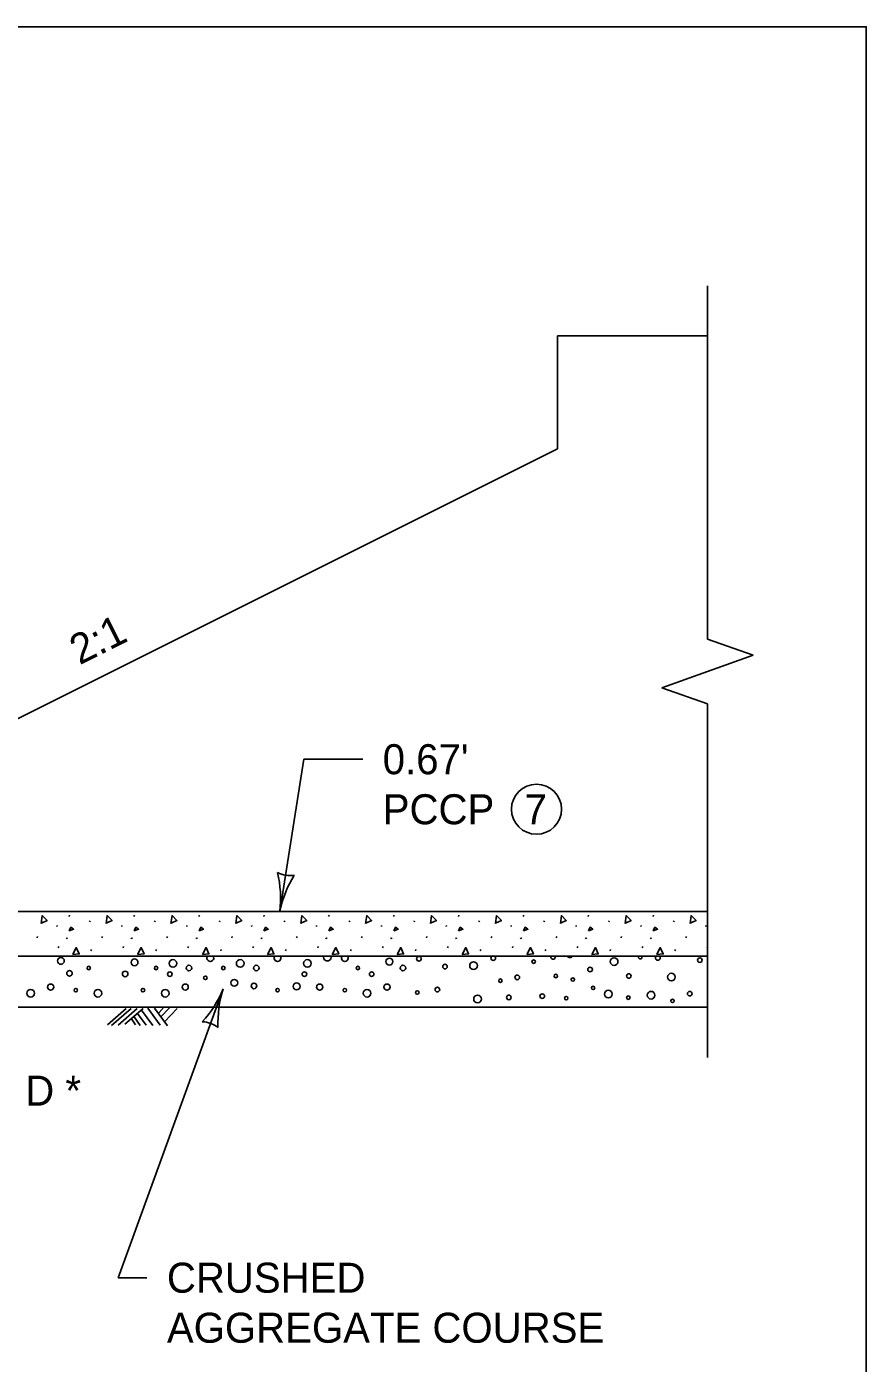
# Model space of a CAD drawing. Extents: x 49991.4 to 50021, y 49987.6 to 50011.4.
# Drawn here: x 50012.898 to 50014.575, y 49989.416 to 49992.087 of the extents above; entities that cross this region are included whole.
import ezdxf

# ---------------------------------------------------------------- set-up
doc = ezdxf.new("R2010")
doc.units = 0
for name, color, linetype in [('Level 1', 7, 'Continuous'), ('Level 2', 7, 'Continuous'), ('Level 3', 7, 'Continuous'), ('Level 6', 7, 'Continuous')]:
    doc.layers.add(name, color=color, linetype=linetype)

msp = doc.modelspace()

# ---------------------------------------------------------------- linework, layer by layer
at = {"layer": 'Level 1'}
for p, q in [((50013.9584, 49991.4692), (50013.9584, 49991.2434)), ((50013.9584, 49991.4692), (50014.2581, 49991.4692)), ((50013.9584, 49991.2434), (50012.1786, 49990.3535)), ((50012.2956, 49990.3188), (50014.2581, 49990.3188)), ((50012.2956, 49990.2297), (50014.2581, 49990.2297)), ((50012.1786, 49990.1273), (50014.2581, 49990.1273)), ((50013.0965, 49990.1248), (50013.0595, 49990.0925)), ((50013.1063, 49990.1248), (50013.0674, 49990.0908)), ((50013.1186, 49990.1249), (50013.0805, 49990.0918)), ((50013.1302, 49990.1252), (50013.0938, 49990.0934)), ((50013.1188, 49990.1152), (50013.1362, 49990.0914)), ((50013.1271, 49990.1218), (50013.1496, 49990.0909)), ((50013.14, 49990.1255), (50013.1646, 49990.0919)), ((50013.1528, 49990.1257), (50013.1788, 49990.0901)), ((50013.1598, 49990.1143), (50013.1706, 49990.1257)), ((50013.1651, 49990.1074), (50013.1835, 49990.1268)), ((50013.1733, 49990.0982), (50013.1987, 49990.1252)), ((50013.1069, 49990.1041), (50013.1153, 49990.0925)), ((50013.1122, 49990.108), (50013.1247, 49990.0908))]:
    msp.add_line(p, q, dxfattribs=at)
msp.add_lwpolyline([(49999.5517, 49992.0867), (50014.5753, 49992.0867), (50014.5753, 49988.387), (49999.5517, 49988.387)], close=True, dxfattribs=at)
for centre, radius in [((50012.966, 49990.22), 0.00684), ((50013.1132, 49990.2171), 0.00684), ((50013.1899, 49990.2149), 0.00766), ((50013.3243, 49990.2149), 0.00766), ((50013.4587, 49990.2149), 0.00766), ((50013.6224, 49990.2185), 0.00684), ((50013.6814, 49990.2243), 0.0046), ((50013.83, 49990.2255), 0.0046), ((50013.9107, 49990.2185), 0.00341), ((50014.0715, 49990.2186), 0.00766), ((50014.2428, 49990.2215), 0.0046), ((50012.9832, 49990.1952), 0.00552), ((50013.0217, 49990.2058), 0.00341), ((50013.0944, 49990.194), 0.00552), ((50013.1562, 49990.2058), 0.00341), ((50013.1837, 49990.1935), 0.0046), ((50013.222, 49990.2058), 0.00552), ((50013.2906, 49990.2058), 0.00341), ((50013.3565, 49990.2058), 0.00552), ((50013.4526, 49990.1935), 0.0046), ((50013.5595, 49990.2058), 0.00341), ((50013.587, 49990.1935), 0.0046), ((50013.6496, 49990.2058), 0.00552), ((50013.7335, 49990.2087), 0.0046), ((50013.7905, 49990.2105), 0.00766), ((50013.8779, 49990.1871), 0.0046), ((50013.955, 49990.1898), 0.00341), ((50014.0234, 49990.2028), 0.0046), ((50014.1009, 49990.1898), 0.0046), ((50014.186, 49990.1877), 0.00766), ((50012.9455, 49990.1676), 0.00613), ((50012.9957, 49990.1615), 0.00341), ((50013.1301, 49990.1615), 0.00341), ((50013.2144, 49990.1676), 0.00613), ((50013.2547, 49990.1861), 0.00341), ((50013.3126, 49990.1762), 0.00684), ((50013.3519, 49990.17), 0.00552), ((50013.399, 49990.1615), 0.00341), ((50013.4371, 49990.1691), 0.00684), ((50013.4832, 49990.1676), 0.00613), ((50013.5334, 49990.1615), 0.00341), ((50013.6177, 49990.1676), 0.00613), ((50013.7183, 49990.1627), 0.0046), ((50013.8442, 49990.1805), 0.00341), ((50013.989, 49990.1826), 0.00341), ((50014.0295, 49990.166), 0.00341), ((50012.9057, 49990.1554), 0.00766), ((50013.0401, 49990.1554), 0.00766), ((50013.1745, 49990.1554), 0.00766), ((50013.5779, 49990.1554), 0.00766), ((50013.6782, 49990.1569), 0.00341), ((50013.7985, 49990.1439), 0.00766), ((50013.861, 49990.1471), 0.0046), ((50013.9279, 49990.1496), 0.0046), ((50013.9759, 49990.1455), 0.00341), ((50014.0599, 49990.1537), 0.00766), ((50014.0998, 49990.1466), 0.00341), ((50014.1453, 49990.1515), 0.00766), ((50014.1881, 49990.1401), 0.00341), ((50014.2225, 49990.1545), 0.0046)]:
    msp.add_circle(centre, radius, dxfattribs=at)
for centre, radius, start, end in [((50013.2646, 49990.2256), 0.00684, 143.5541, 36.4459), ((50013.399, 49990.2256), 0.00684, 143.5541, 36.4459), ((50013.4984, 49990.2275), 0.00765, 163.8349, 16.1651), ((50013.5334, 49990.2256), 0.00684, 143.5541, 36.4459), ((50013.9495, 49990.228), 0.0046, 159.2385, 20.7615), ((50013.9831, 49990.2345), 0.00766, 219.0724, 320.9276), ((50014.1236, 49990.2273), 0.00341, 135.9278, 44.0722), ((50014.1588, 49990.2259), 0.0046, 125.7802, 54.2198)]:
    msp.add_arc(centre, radius, start, end, dxfattribs=at)
at = {"layer": 'Level 2'}
msp.add_circle((50013.9164, 49990.523), 0.05, dxfattribs=at)
at = {"layer": 'Level 3'}
for p, q in [((50013.4037, 49990.3188), (50013.4515, 49990.623)), ((50013.4515, 49990.623), (50013.5691, 49990.623)), ((50012.9823, 49990.3089), (50012.9834, 49990.3113)), ((50013.0235, 49990.2978), (50013.0245, 49990.3002)), ((50013.112, 49990.3089), (50013.1131, 49990.3113)), ((50013.1531, 49990.2978), (50013.1542, 49990.3002)), ((50013.2416, 49990.3089), (50013.2427, 49990.3113)), ((50013.2828, 49990.2978), (50013.2839, 49990.3002)), ((50013.3713, 49990.3089), (50013.3724, 49990.3113)), ((50013.4124, 49990.2978), (50013.4135, 49990.3002)), ((50013.5009, 49990.3089), (50013.502, 49990.3113)), ((50013.5421, 49990.2978), (50013.5432, 49990.3002)), ((50013.6306, 49990.3089), (50013.6317, 49990.3113)), ((50013.6717, 49990.2978), (50013.6728, 49990.3002)), ((50013.7602, 49990.3089), (50013.7613, 49990.3113)), ((50013.8014, 49990.2978), (50013.8025, 49990.3002)), ((50013.8899, 49990.3089), (50013.891, 49990.3113)), ((50013.931, 49990.2978), (50013.9321, 49990.3002)), ((50014.0196, 49990.3089), (50014.0206, 49990.3113)), ((50014.0607, 49990.2978), (50014.0618, 49990.3002)), ((50014.1492, 49990.3089), (50014.1503, 49990.3113)), ((50014.1904, 49990.2978), (50014.1914, 49990.3002)), ((50012.9582, 49990.291), (50012.9584, 49990.2885)), ((50013.0878, 49990.291), (50013.0881, 49990.2885)), ((50013.2175, 49990.291), (50013.2177, 49990.2885)), ((50013.3471, 49990.291), (50013.3474, 49990.2885)), ((50013.4768, 49990.291), (50013.477, 49990.2885)), ((50013.6064, 49990.291), (50013.6067, 49990.2885)), ((50013.7361, 49990.291), (50013.7364, 49990.2885)), ((50013.8657, 49990.291), (50013.866, 49990.2885)), ((50013.9954, 49990.291), (50013.9957, 49990.2885)), ((50014.1251, 49990.291), (50014.1253, 49990.2885)), ((50014.2547, 49990.291), (50014.255, 49990.2885)), ((50012.9184, 49990.2664), (50012.9195, 49990.2688)), ((50012.9607, 49990.2463), (50012.9617, 49990.2487)), ((50012.9766, 49990.2664), (50012.9777, 49990.2647)), ((50012.9777, 49990.2658), (50012.9788, 49990.2641)), ((50013.0481, 49990.2664), (50013.0492, 49990.2688)), ((50013.0903, 49990.2463), (50013.0914, 49990.2487)), ((50013.1063, 49990.2664), (50013.1074, 49990.2647)), ((50013.1074, 49990.2658), (50013.1085, 49990.2641)), ((50013.1777, 49990.2664), (50013.1788, 49990.2688)), ((50013.22, 49990.2463), (50013.2211, 49990.2487)), ((50013.2359, 49990.2664), (50013.237, 49990.2647)), ((50013.237, 49990.2658), (50013.2381, 49990.2641)), ((50013.3074, 49990.2664), (50013.3085, 49990.2688)), ((50013.3496, 49990.2463), (50013.3507, 49990.2487)), ((50013.3656, 49990.2664), (50013.3667, 49990.2647)), ((50013.3667, 49990.2658), (50013.3678, 49990.2641)), ((50013.4371, 49990.2664), (50013.4381, 49990.2688)), ((50013.4793, 49990.2463), (50013.4804, 49990.2487)), ((50013.4953, 49990.2664), (50013.4963, 49990.2647)), ((50013.4963, 49990.2658), (50013.4974, 49990.2641)), ((50013.5667, 49990.2664), (50013.5678, 49990.2688)), ((50013.6089, 49990.2463), (50013.61, 49990.2487)), ((50013.6249, 49990.2664), (50013.626, 49990.2647)), ((50013.626, 49990.2658), (50013.6271, 49990.2641)), ((50013.6964, 49990.2664), (50013.6974, 49990.2688)), ((50013.7386, 49990.2463), (50013.7397, 49990.2487)), ((50013.7546, 49990.2664), (50013.7556, 49990.2647)), ((50013.7556, 49990.2658), (50013.7567, 49990.2641)), ((50013.826, 49990.2664), (50013.8271, 49990.2688)), ((50013.8682, 49990.2463), (50013.8693, 49990.2487)), ((50013.8842, 49990.2664), (50013.8853, 49990.2647)), ((50013.8853, 49990.2658), (50013.8864, 49990.2641)), ((50013.9557, 49990.2664), (50013.9568, 49990.2688)), ((50013.9979, 49990.2463), (50013.999, 49990.2487)), ((50014.0139, 49990.2664), (50014.015, 49990.2647)), ((50014.015, 49990.2658), (50014.016, 49990.2641)), ((50014.0853, 49990.2664), (50014.0864, 49990.2688)), ((50014.1276, 49990.2463), (50014.1286, 49990.2487)), ((50014.1435, 49990.2664), (50014.1446, 49990.2647)), ((50014.1446, 49990.2658), (50014.1457, 49990.2641)), ((50014.215, 49990.2664), (50014.2161, 49990.2688)), ((50014.2572, 49990.2463), (50014.2581, 49990.2483)), ((50013.0262, 49990.2401), (50013.0273, 49990.2425)), ((50013.1558, 49990.2401), (50013.1569, 49990.2425)), ((50013.2855, 49990.2401), (50013.2866, 49990.2425)), ((50013.4151, 49990.2401), (50013.4162, 49990.2425)), ((50013.5448, 49990.2401), (50013.5459, 49990.2425)), ((50013.6744, 49990.2401), (50013.6755, 49990.2425)), ((50013.8041, 49990.2401), (50013.8052, 49990.2425)), ((50013.9338, 49990.2401), (50013.9348, 49990.2425)), ((50014.0634, 49990.2401), (50014.0645, 49990.2425)), ((50014.1931, 49990.2401), (50014.1941, 49990.2425)), ((50013.2902, 49990.164), (50013.0805, 49989.587)), ((50013.0805, 49989.587), (50013.1379, 49989.587))]:
    msp.add_line(p, q, dxfattribs=at)
for points in [[(50012.9267, 49990.295), (50012.9289, 49990.3104), (50012.9386, 49990.3004), (50012.927, 49990.2951)], [(50013.0564, 49990.295), (50013.0585, 49990.3104), (50013.0682, 49990.3004), (50013.0566, 49990.2951)], [(50013.186, 49990.295), (50013.1882, 49990.3104), (50013.1979, 49990.3004), (50013.1863, 49990.2951)], [(50013.3157, 49990.295), (50013.3178, 49990.3104), (50013.3275, 49990.3004), (50013.316, 49990.2951)], [(50013.4454, 49990.295), (50013.4475, 49990.3104), (50013.4572, 49990.3004), (50013.4456, 49990.2951)], [(50013.575, 49990.295), (50013.5772, 49990.3104), (50013.5868, 49990.3004), (50013.5753, 49990.2951)], [(50013.7047, 49990.295), (50013.7068, 49990.3104), (50013.7165, 49990.3004), (50013.7049, 49990.2951)], [(50013.8343, 49990.295), (50013.8365, 49990.3104), (50013.8462, 49990.3004), (50013.8346, 49990.2951)], [(50013.964, 49990.295), (50013.9661, 49990.3104), (50013.9758, 49990.3004), (50013.9642, 49990.2951)], [(50014.0936, 49990.295), (50014.0958, 49990.3104), (50014.1055, 49990.3004), (50014.0939, 49990.2951)], [(50014.2233, 49990.295), (50014.2254, 49990.3104), (50014.2351, 49990.3004), (50014.2235, 49990.2951)], [(50012.9829, 49990.2804), (50012.9861, 49990.2872), (50012.9915, 49990.2832), (50012.9829, 49990.2804)], [(50013.1125, 49990.2804), (50013.1158, 49990.2872), (50013.1212, 49990.2832), (50013.1125, 49990.2804)], [(50013.2422, 49990.2804), (50013.2454, 49990.2872), (50013.2508, 49990.2832), (50013.2422, 49990.2804)], [(50013.3718, 49990.2804), (50013.3751, 49990.2872), (50013.3805, 49990.2832), (50013.3718, 49990.2804)], [(50013.5015, 49990.2804), (50013.5047, 49990.2872), (50013.5101, 49990.2832), (50013.5015, 49990.2804)], [(50013.6311, 49990.2804), (50013.6344, 49990.2872), (50013.6398, 49990.2832), (50013.6311, 49990.2804)], [(50013.7608, 49990.2804), (50013.764, 49990.2872), (50013.7695, 49990.2832), (50013.7608, 49990.2804)], [(50013.8904, 49990.2804), (50013.8937, 49990.2872), (50013.8991, 49990.2832), (50013.8904, 49990.2804)], [(50014.0201, 49990.2804), (50014.0233, 49990.2872), (50014.0288, 49990.2832), (50014.0201, 49990.2804)], [(50014.1498, 49990.2804), (50014.153, 49990.2872), (50014.1584, 49990.2832), (50014.1498, 49990.2804)], [(50012.9896, 49990.2328), (50012.9969, 49990.2466), (50013.0026, 49990.2339), (50012.9899, 49990.2328)], [(50013.1193, 49990.2328), (50013.1266, 49990.2466), (50013.1323, 49990.2339), (50013.1196, 49990.2328)], [(50013.2489, 49990.2328), (50013.2562, 49990.2466), (50013.2619, 49990.2339), (50013.2492, 49990.2328)], [(50013.3786, 49990.2328), (50013.3859, 49990.2466), (50013.3916, 49990.2339), (50013.3789, 49990.2328)], [(50013.5082, 49990.2328), (50013.5156, 49990.2466), (50013.5212, 49990.2339), (50013.5085, 49990.2328)], [(50013.6379, 49990.2328), (50013.6452, 49990.2466), (50013.6509, 49990.2339), (50013.6382, 49990.2328)], [(50013.7676, 49990.2328), (50013.7749, 49990.2466), (50013.7806, 49990.2339), (50013.7678, 49990.2328)], [(50013.8972, 49990.2328), (50013.9045, 49990.2466), (50013.9102, 49990.2339), (50013.8975, 49990.2328)], [(50014.0269, 49990.2328), (50014.0342, 49990.2466), (50014.0399, 49990.2339), (50014.0271, 49990.2328)], [(50014.1565, 49990.2328), (50014.1638, 49990.2466), (50014.1695, 49990.2339), (50014.1568, 49990.2328)]]:
    msp.add_lwpolyline(points, dxfattribs=at)
for centre, radius, start, end in [((50013.4236, 49990.4454), 0.0548, 243.2047, 278.927), ((50013.172, 49990.3435), 0.233, 353.8932, 13.143), ((50013.6217, 49990.2752), 0.2223, 148.5219, 168.7054), ((50013.0846, 49990.2484), 0.2223, 317.4833, 337.6668), ((50013.5128, 49990.0953), 0.233, 162.8546, 182.1044), ((50013.2464, 49990.0435), 0.0548, 52.1661, 87.8884)]:
    msp.add_arc(centre, radius, start, end, dxfattribs=at)
at = {"layer": 'Level 6'}
for p, q in [((50014.2581, 49991.5692), (50014.2581, 49990.863)), ((50014.3495, 49990.8306), (50014.2581, 49990.863)), ((50014.3495, 49990.8306), (50014.2581, 49990.7982)), ((50014.2581, 49990.7982), (50014.1667, 49990.7658)), ((50014.2581, 49990.7334), (50014.1667, 49990.7658)), ((50014.2581, 49990.7334), (50014.2581, 49990.0273))]:
    msp.add_line(p, q, dxfattribs=at)

# ---------------------------------------------------------------- texts
at = {"layer": 'Level 2'}
msp.add_text('2:1', height=0.06, rotation=26.5651, dxfattribs=at).set_placement((50013.0033, 49990.8105))
for s, p in [("0.67'", (50013.6091, 49990.593)), ('PCCP', (50013.6091, 49990.493)), ('7', (50013.8926, 49990.493)), ('D *', (50012.8948, 49989.9308)), ('CRUSHED', (50013.1779, 49989.557)), ('AGGREGATE COURSE', (50013.1779, 49989.457))]:
    msp.add_text(s, height=0.06, dxfattribs=at).set_placement(p)

doc.saveas('drawing.dxf')
